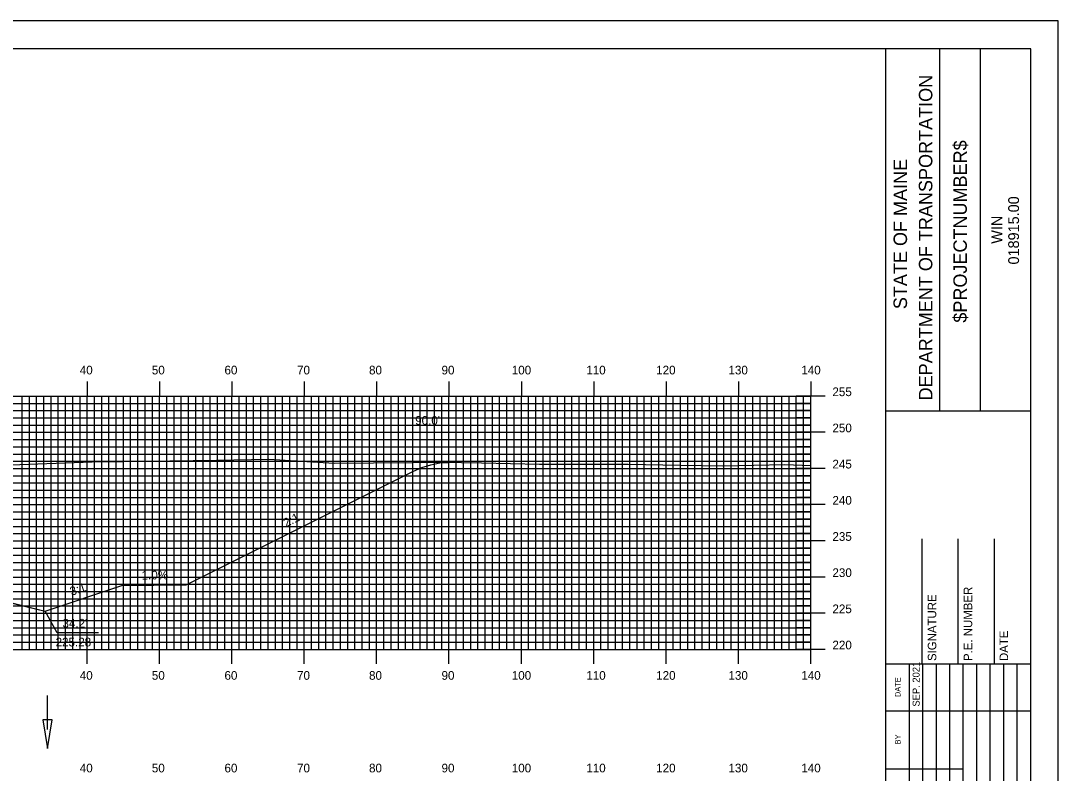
# Model space of a CAD drawing. Extents: x 1817276 to 1817620, y 442591 to 442811.
# Drawn here: x 1817472.9 to 1817616.3, y 442706.6 to 442810.5 of the extents above; entities that cross this region are included whole.
import ezdxf

# ---------------------------------------------------------------- set-up
doc = ezdxf.new("R2010")
doc.units = 0
for name, color, linetype in [('ANNOTATION', 7, 'Continuous'), ('BORDER', 7, 'Continuous'), ('D_Drainage_Ditch_Line', 7, 'Continuous'), ('D_Roadway_Centerline', 7, 'Continuous'), ('D_Roadway_SlopeLines', 7, 'Continuous'), ('D_Text_Standard', 7, 'Continuous'), ('H_V ANNOTATION', 7, 'Continuous'), ('MAJOR', 7, 'Continuous'), ('MINOR', 7, 'Continuous'), ('PLOT BOUNDARY', 7, 'Continuous'), ('S_Roadway_Centerline', 7, 'Continuous')]:
    doc.layers.add(name, color=color, linetype=linetype)

msp = doc.modelspace()

# ---------------------------------------------------------------- linework, layer by layer
at = {"layer": 'ANNOTATION'}
msp.add_lwpolyline([(1817483.64, 442725.95), (1817477.95, 442725.95), (1817476.27, 442728.94)], dxfattribs=at)
at = {"layer": 'BORDER'}
for p, q in [((1817592.5, 442596.67), (1817592.5, 442806.67)), ((1817599.96, 442756.66), (1817599.96, 442806.66)), ((1817605.55, 442756.66), (1817605.55, 442806.66)), ((1817592.5, 442756.65), (1817612.5, 442756.65)), ((1817597.5, 442721.67), (1817597.5, 442738.97)), ((1817602.5, 442721.67), (1817602.5, 442738.97)), ((1817607.5, 442721.67), (1817607.5, 442738.97)), ((1817592.5, 442721.67), (1817612.5, 442721.67))]:
    msp.add_line(p, q, dxfattribs=at)
msp.add_lwpolyline([(1817292.5, 442596.67), (1817612.5, 442596.67), (1817612.5, 442806.67), (1817292.5, 442806.67)], close=True, dxfattribs=at)
for points in [[(1817595.73, 442715.17), (1817595.73, 442721.67)], [(1817597.59, 442686.68), (1817597.59, 442721.67)], [(1817599.46, 442721.67), (1817599.46, 442686.68)], [(1817601.32, 442686.68), (1817601.32, 442721.67)], [(1817603.18, 442686.68), (1817603.18, 442721.67)], [(1817605.05, 442686.68), (1817605.05, 442721.67)], [(1817606.91, 442686.68), (1817606.91, 442721.67)], [(1817608.77, 442686.68), (1817608.77, 442721.67)], [(1817610.64, 442686.68), (1817610.64, 442721.67)], [(1817595.73, 442686.68), (1817595.73, 442720.26)], [(1817592.5, 442715.17), (1817612.5, 442715.17)], [(1817592.5, 442707.17), (1817595.73, 442707.17)], [(1817595.73, 442707.17), (1817603.18, 442707.17)]]:
    msp.add_lwpolyline(points, dxfattribs=at)
at = {"layer": 'D_Drainage_Ditch_Line'}
msp.add_line((1817476.6, 442712.61), (1817476.6, 442717.31), dxfattribs=at)
msp.add_lwpolyline([(1817477.26, 442713.92), (1817475.95, 442713.92), (1817476.6, 442709.99)], close=True, dxfattribs=at)
at = {"layer": 'D_Roadway_Centerline'}
msp.add_lwpolyline([(1817352.1, 442743.88), (1817353.35, 442743.89), (1817354.6, 442743.72), (1817355.85, 442743.37), (1817357.1, 442742.84), (1817377.4, 442732.69), (1817397.29, 442732.49), (1817407.93, 442728.94), (1817411.93, 442729.94), (1817422.1, 442732.49), (1817430.1, 442732.81), (1817442.1, 442733.05), (1817454.1, 442732.81), (1817462.1, 442732.49), (1817472.27, 442729.94), (1817476.27, 442728.94), (1817486.9, 442732.49), (1817495.76, 442732.58), (1817527.1, 442748.25), (1817528.35, 442748.79), (1817529.6, 442749.19), (1817530.85, 442749.43), (1817532.1, 442749.51)], dxfattribs=at)
at = {"layer": 'D_Roadway_SlopeLines'}
for points in [[(1817486.9, 442732.49), (1817495.76, 442732.58), (1817527.1, 442748.25), (1817528.35, 442748.79), (1817529.6, 442749.19), (1817530.85, 442749.43), (1817532.1, 442749.51)], [(1817462.1, 442732.49), (1817476.27, 442728.94)], [(1817476.27, 442728.94), (1817486.9, 442732.49)]]:
    msp.add_lwpolyline(points, dxfattribs=at)
at = {"layer": 'MAJOR'}
for p, q in [((1817482.1, 442760.67), (1817482.1, 442758.67)), ((1817492.1, 442760.67), (1817492.1, 442758.67)), ((1817502.1, 442760.67), (1817502.1, 442758.67)), ((1817512.1, 442760.67), (1817512.1, 442758.67)), ((1817522.1, 442760.67), (1817522.1, 442758.67)), ((1817532.1, 442760.67), (1817532.1, 442758.67)), ((1817542.1, 442760.67), (1817542.1, 442758.67)), ((1817552.1, 442760.67), (1817552.1, 442758.67)), ((1817562.1, 442760.67), (1817562.1, 442758.67)), ((1817572.1, 442760.67), (1817572.1, 442758.67)), ((1817582.1, 442760.67), (1817582.1, 442758.67)), ((1817302.1, 442758.67), (1817582.1, 442758.67)), ((1817302.1, 442758.67), (1817582.1, 442758.67)), ((1817482.1, 442723.67), (1817482.1, 442758.67)), ((1817492.1, 442723.67), (1817492.1, 442758.67)), ((1817502.1, 442723.67), (1817502.1, 442758.67)), ((1817512.1, 442723.67), (1817512.1, 442758.67)), ((1817522.1, 442723.67), (1817522.1, 442758.67)), ((1817532.1, 442723.67), (1817532.1, 442758.67)), ((1817542.1, 442723.67), (1817542.1, 442758.67)), ((1817552.1, 442723.67), (1817552.1, 442758.67)), ((1817562.1, 442723.67), (1817562.1, 442758.67)), ((1817572.1, 442723.67), (1817572.1, 442758.67)), ((1817584.1, 442758.67), (1817580.1, 442758.67)), ((1817582.1, 442723.67), (1817582.1, 442758.67)), ((1817582.1, 442723.67), (1817582.1, 442758.67)), ((1817302.1, 442753.67), (1817582.1, 442753.67)), ((1817584.1, 442753.67), (1817580.1, 442753.67)), ((1817302.1, 442748.67), (1817582.1, 442748.67)), ((1817584.1, 442748.67), (1817580.1, 442748.67)), ((1817302.1, 442743.67), (1817582.1, 442743.67)), ((1817584.1, 442743.67), (1817580.1, 442743.67)), ((1817302.1, 442738.67), (1817582.1, 442738.67)), ((1817584.1, 442738.67), (1817580.1, 442738.67)), ((1817302.1, 442733.67), (1817582.1, 442733.67)), ((1817584.1, 442733.67), (1817580.1, 442733.67)), ((1817302.1, 442728.67), (1817582.1, 442728.67)), ((1817584.1, 442728.67), (1817580.1, 442728.67)), ((1817302.1, 442723.67), (1817582.1, 442723.67)), ((1817302.1, 442723.67), (1817582.1, 442723.67)), ((1817482.1, 442721.66), (1817482.1, 442723.67)), ((1817492.1, 442721.66), (1817492.1, 442723.67)), ((1817502.1, 442721.66), (1817502.1, 442723.67)), ((1817512.1, 442721.66), (1817512.1, 442723.67)), ((1817522.1, 442721.66), (1817522.1, 442723.67)), ((1817532.1, 442721.66), (1817532.1, 442723.67)), ((1817542.1, 442721.66), (1817542.1, 442723.67)), ((1817552.1, 442721.66), (1817552.1, 442723.67)), ((1817562.1, 442721.66), (1817562.1, 442723.67)), ((1817572.1, 442721.66), (1817572.1, 442723.67)), ((1817584.1, 442723.67), (1817580.1, 442723.67)), ((1817582.1, 442721.66), (1817582.1, 442723.67))]:
    msp.add_line(p, q, dxfattribs=at)
at = {"layer": 'MINOR'}
for p, q in [((1817473.1, 442723.67), (1817473.1, 442758.67)), ((1817474.1, 442723.67), (1817474.1, 442758.67)), ((1817475.1, 442723.67), (1817475.1, 442758.67)), ((1817476.1, 442723.67), (1817476.1, 442758.67)), ((1817477.1, 442723.67), (1817477.1, 442758.67)), ((1817478.1, 442723.67), (1817478.1, 442758.67)), ((1817479.1, 442723.67), (1817479.1, 442758.67)), ((1817480.1, 442723.67), (1817480.1, 442758.67)), ((1817481.1, 442723.67), (1817481.1, 442758.67)), ((1817483.1, 442723.67), (1817483.1, 442758.67)), ((1817484.1, 442723.67), (1817484.1, 442758.67)), ((1817485.1, 442723.67), (1817485.1, 442758.67)), ((1817486.1, 442723.67), (1817486.1, 442758.67)), ((1817487.1, 442723.67), (1817487.1, 442758.67)), ((1817488.1, 442723.67), (1817488.1, 442758.67)), ((1817489.1, 442723.67), (1817489.1, 442758.67)), ((1817490.1, 442723.67), (1817490.1, 442758.67)), ((1817491.1, 442723.67), (1817491.1, 442758.67)), ((1817493.1, 442723.67), (1817493.1, 442758.67)), ((1817494.1, 442723.67), (1817494.1, 442758.67)), ((1817495.1, 442723.67), (1817495.1, 442758.67)), ((1817496.1, 442723.67), (1817496.1, 442758.67)), ((1817497.1, 442723.67), (1817497.1, 442758.67)), ((1817498.1, 442723.67), (1817498.1, 442758.67)), ((1817499.1, 442723.67), (1817499.1, 442758.67)), ((1817500.1, 442723.67), (1817500.1, 442758.67)), ((1817501.1, 442723.67), (1817501.1, 442758.67)), ((1817503.1, 442723.67), (1817503.1, 442758.67)), ((1817504.1, 442723.67), (1817504.1, 442758.67)), ((1817505.1, 442723.67), (1817505.1, 442758.67)), ((1817506.1, 442723.67), (1817506.1, 442758.67)), ((1817507.1, 442723.67), (1817507.1, 442758.67)), ((1817508.1, 442723.67), (1817508.1, 442758.67)), ((1817509.1, 442723.67), (1817509.1, 442758.67)), ((1817510.1, 442723.67), (1817510.1, 442758.67)), ((1817511.1, 442723.67), (1817511.1, 442758.67)), ((1817513.1, 442723.67), (1817513.1, 442758.67)), ((1817514.1, 442723.67), (1817514.1, 442758.67)), ((1817515.1, 442723.67), (1817515.1, 442758.67)), ((1817516.1, 442723.67), (1817516.1, 442758.67)), ((1817517.1, 442723.67), (1817517.1, 442758.67)), ((1817518.1, 442723.67), (1817518.1, 442758.67)), ((1817519.1, 442723.67), (1817519.1, 442758.67)), ((1817520.1, 442723.67), (1817520.1, 442758.67)), ((1817521.1, 442723.67), (1817521.1, 442758.67)), ((1817523.1, 442723.67), (1817523.1, 442758.67)), ((1817524.1, 442723.67), (1817524.1, 442758.67)), ((1817525.1, 442723.67), (1817525.1, 442758.67)), ((1817526.1, 442723.67), (1817526.1, 442758.67)), ((1817527.1, 442723.67), (1817527.1, 442758.67)), ((1817528.1, 442723.67), (1817528.1, 442758.67)), ((1817529.1, 442723.67), (1817529.1, 442758.67)), ((1817530.1, 442723.67), (1817530.1, 442758.67)), ((1817531.1, 442723.67), (1817531.1, 442758.67)), ((1817533.1, 442723.67), (1817533.1, 442758.67)), ((1817534.1, 442723.67), (1817534.1, 442758.67)), ((1817535.1, 442723.67), (1817535.1, 442758.67)), ((1817536.1, 442723.67), (1817536.1, 442758.67)), ((1817537.1, 442723.67), (1817537.1, 442758.67)), ((1817538.1, 442723.67), (1817538.1, 442758.67)), ((1817539.1, 442723.67), (1817539.1, 442758.67)), ((1817540.1, 442723.67), (1817540.1, 442758.67)), ((1817541.1, 442723.67), (1817541.1, 442758.67)), ((1817543.1, 442723.67), (1817543.1, 442758.67)), ((1817544.1, 442723.67), (1817544.1, 442758.67)), ((1817545.1, 442723.67), (1817545.1, 442758.67)), ((1817546.1, 442723.67), (1817546.1, 442758.67)), ((1817547.1, 442723.67), (1817547.1, 442758.67)), ((1817548.1, 442723.67), (1817548.1, 442758.67)), ((1817549.1, 442723.67), (1817549.1, 442758.67)), ((1817550.1, 442723.67), (1817550.1, 442758.67)), ((1817551.1, 442723.67), (1817551.1, 442758.67)), ((1817553.1, 442723.67), (1817553.1, 442758.67)), ((1817554.1, 442723.67), (1817554.1, 442758.67)), ((1817555.1, 442723.67), (1817555.1, 442758.67)), ((1817556.1, 442723.67), (1817556.1, 442758.67)), ((1817557.1, 442723.67), (1817557.1, 442758.67)), ((1817558.1, 442723.67), (1817558.1, 442758.67)), ((1817559.1, 442723.67), (1817559.1, 442758.67)), ((1817560.1, 442723.67), (1817560.1, 442758.67)), ((1817561.1, 442723.67), (1817561.1, 442758.67)), ((1817563.1, 442723.67), (1817563.1, 442758.67)), ((1817564.1, 442723.67), (1817564.1, 442758.67)), ((1817565.1, 442723.67), (1817565.1, 442758.67)), ((1817566.1, 442723.67), (1817566.1, 442758.67)), ((1817567.1, 442723.67), (1817567.1, 442758.67)), ((1817568.1, 442723.67), (1817568.1, 442758.67)), ((1817569.1, 442723.67), (1817569.1, 442758.67)), ((1817570.1, 442723.67), (1817570.1, 442758.67)), ((1817571.1, 442723.67), (1817571.1, 442758.67)), ((1817573.1, 442723.67), (1817573.1, 442758.67)), ((1817574.1, 442723.67), (1817574.1, 442758.67)), ((1817575.1, 442723.67), (1817575.1, 442758.67)), ((1817576.1, 442723.67), (1817576.1, 442758.67)), ((1817577.1, 442723.67), (1817577.1, 442758.67)), ((1817578.1, 442723.67), (1817578.1, 442758.67)), ((1817579.1, 442723.67), (1817579.1, 442758.67)), ((1817580.1, 442723.67), (1817580.1, 442758.67)), ((1817581.1, 442723.67), (1817581.1, 442758.67)), ((1817302.1, 442757.67), (1817582.1, 442757.67)), ((1817582.1, 442757.67), (1817580.1, 442757.67)), ((1817302.1, 442756.67), (1817582.1, 442756.67)), ((1817302.1, 442755.67), (1817582.1, 442755.67)), ((1817582.1, 442756.67), (1817580.1, 442756.67)), ((1817582.1, 442755.67), (1817580.1, 442755.67)), ((1817302.1, 442754.67), (1817582.1, 442754.67)), ((1817582.1, 442754.67), (1817580.1, 442754.67)), ((1817302.1, 442752.67), (1817582.1, 442752.67)), ((1817582.1, 442752.67), (1817580.1, 442752.67)), ((1817302.1, 442751.67), (1817582.1, 442751.67)), ((1817582.1, 442751.67), (1817580.1, 442751.67)), ((1817302.1, 442750.67), (1817582.1, 442750.67)), ((1817582.1, 442750.67), (1817580.1, 442750.67)), ((1817302.1, 442749.67), (1817582.1, 442749.67)), ((1817582.1, 442749.67), (1817580.1, 442749.67)), ((1817302.1, 442747.67), (1817582.1, 442747.67)), ((1817582.1, 442747.67), (1817580.1, 442747.67)), ((1817302.1, 442746.67), (1817582.1, 442746.67)), ((1817302.1, 442745.67), (1817582.1, 442745.67)), ((1817582.1, 442746.67), (1817580.1, 442746.67)), ((1817582.1, 442745.67), (1817580.1, 442745.67)), ((1817302.1, 442744.67), (1817582.1, 442744.67)), ((1817582.1, 442744.67), (1817580.1, 442744.67)), ((1817302.1, 442742.67), (1817582.1, 442742.67)), ((1817582.1, 442742.67), (1817580.1, 442742.67)), ((1817302.1, 442741.67), (1817582.1, 442741.67)), ((1817582.1, 442741.67), (1817580.1, 442741.67)), ((1817302.1, 442740.67), (1817582.1, 442740.67)), ((1817582.1, 442740.67), (1817580.1, 442740.67)), ((1817302.1, 442739.67), (1817582.1, 442739.67)), ((1817582.1, 442739.67), (1817580.1, 442739.67)), ((1817302.1, 442737.67), (1817582.1, 442737.67)), ((1817582.1, 442737.67), (1817580.1, 442737.67)), ((1817302.1, 442736.67), (1817582.1, 442736.67)), ((1817302.1, 442735.67), (1817582.1, 442735.67)), ((1817582.1, 442736.67), (1817580.1, 442736.67)), ((1817582.1, 442735.67), (1817580.1, 442735.67)), ((1817302.1, 442734.67), (1817582.1, 442734.67)), ((1817582.1, 442734.67), (1817580.1, 442734.67)), ((1817302.1, 442732.67), (1817582.1, 442732.67)), ((1817582.1, 442732.67), (1817580.1, 442732.67)), ((1817302.1, 442731.67), (1817582.1, 442731.67)), ((1817582.1, 442731.67), (1817580.1, 442731.67)), ((1817302.1, 442730.67), (1817582.1, 442730.67)), ((1817582.1, 442730.67), (1817580.1, 442730.67)), ((1817302.1, 442729.67), (1817582.1, 442729.67)), ((1817582.1, 442729.67), (1817580.1, 442729.67)), ((1817302.1, 442727.67), (1817582.1, 442727.67)), ((1817582.1, 442727.67), (1817580.1, 442727.67)), ((1817302.1, 442726.67), (1817582.1, 442726.67)), ((1817302.1, 442725.67), (1817582.1, 442725.67)), ((1817582.1, 442726.67), (1817580.1, 442726.67)), ((1817582.1, 442725.67), (1817580.1, 442725.67)), ((1817302.1, 442724.67), (1817582.1, 442724.67)), ((1817582.1, 442724.67), (1817580.1, 442724.67))]:
    msp.add_line(p, q, dxfattribs=at)
at = {"layer": 'PLOT BOUNDARY'}
msp.add_lwpolyline([(1817276.31, 442590.55), (1817616.31, 442590.55), (1817616.31, 442810.55), (1817276.31, 442810.55)], close=True, dxfattribs=at)
at = {"layer": 'S_Roadway_Centerline'}
msp.add_lwpolyline([(1817471.56, 442749.19), (1817482.76, 442749.6), (1817487.02, 442749.65), (1817499.98, 442749.84), (1817507.22, 442749.94), (1817516.25, 442749.4), (1817532.57, 442749.52), (1817533.85, 442749.5), (1817536.61, 442749.45), (1817544.62, 442749.27), (1817552.43, 442749.27), (1817556.86, 442749.27), (1817564.07, 442749.12), (1817569.95, 442749.05), (1817578.5, 442749.23), (1817582.1, 442749.06)], dxfattribs=at)

# ---------------------------------------------------------------- texts
at = {"layer": 'ANNOTATION'}
for s, rotation, p in [('2:1', 26.5651, (1817509.57, 442740.52)), ('1.0%', 0.5729, (1817489.62, 442733.32)), ('3:1', 18.4349, (1817479.93, 442731.07))]:
    msp.add_text(s, height=1.2, rotation=rotation, dxfattribs=at).set_placement(p)
for s, p in [("34.2'", (1817478.68, 442726.68)), ('225.28', (1817477.73, 442724.08))]:
    msp.add_text(s, height=1.2, dxfattribs=at).set_placement(p)
at = {"layer": 'BORDER'}
for s, height, p in [('DEPARTMENT OF TRANSPORTATION', 1.8635, (1817598.91, 442758.08)), ('$PROJECTNUMBER$', 1.8635, (1817603.68, 442768.82)), ('STATE OF MAINE', 1.8635, (1817595.41, 442770.69)), ('018915.00', 1.491, (1817610.89, 442776.86)), ('WIN', 1.491, (1817608.57, 442779.73)), ('SIGNATURE', 1.181, (1817599.46, 442722.06)), ('P.E. NUMBER', 1.1811, (1817604.42, 442722.06)), ('DATE', 1.181, (1817609.38, 442722.06)), ('SEP. 2021', 0.969, (1817597.15, 442715.76)), ('DATE', 0.743, (1817594.51, 442717.08)), ('BY', 0.743, (1817594.51, 442710.54))]:
    msp.add_text(s, height=height, rotation=90, dxfattribs=at).set_placement(p)
at = {"layer": 'D_Text_Standard'}
msp.add_text("90.0'", height=1.2, dxfattribs=at).set_placement((1817527.43, 442754.71))
at = {"layer": 'H_V ANNOTATION'}
for s, p in [('40', (1817481.07, 442761.67)), ('50', (1817491.03, 442761.67)), ('60', (1817501.07, 442761.67)), ('70', (1817511.1, 442761.67)), ('80', (1817521.05, 442761.67)), ('90', (1817531.07, 442761.67)), ('100', (1817540.78, 442761.67)), ('110', (1817551.08, 442761.67)), ('120', (1817560.74, 442761.67)), ('130', (1817570.73, 442761.67)), ('140', (1817580.8, 442761.67)), ('255', (1817585.1, 442758.67)), ('250', (1817585.1, 442753.67)), ('245', (1817585.1, 442748.67)), ('240', (1817585.1, 442743.67)), ('235', (1817585.1, 442738.67)), ('230', (1817585.1, 442733.67)), ('225', (1817585.1, 442728.67)), ('220', (1817585.1, 442723.67)), ('40', (1817481.07, 442719.47)), ('50', (1817491.03, 442719.47)), ('60', (1817501.07, 442719.47)), ('70', (1817511.1, 442719.47)), ('80', (1817521.05, 442719.47)), ('90', (1817531.07, 442719.47)), ('100', (1817540.78, 442719.47)), ('110', (1817551.08, 442719.47)), ('120', (1817560.74, 442719.47)), ('130', (1817570.73, 442719.47)), ('140', (1817580.8, 442719.47)), ('40', (1817481.07, 442706.67)), ('50', (1817491.03, 442706.67)), ('60', (1817501.07, 442706.67)), ('70', (1817511.1, 442706.67)), ('80', (1817521.05, 442706.67)), ('90', (1817531.07, 442706.67)), ('100', (1817540.78, 442706.67)), ('110', (1817551.08, 442706.67)), ('120', (1817560.74, 442706.67)), ('130', (1817570.73, 442706.67)), ('140', (1817580.8, 442706.67))]:
    msp.add_text(s, height=1.2, dxfattribs=at).set_placement(p)

doc.saveas('drawing.dxf')
